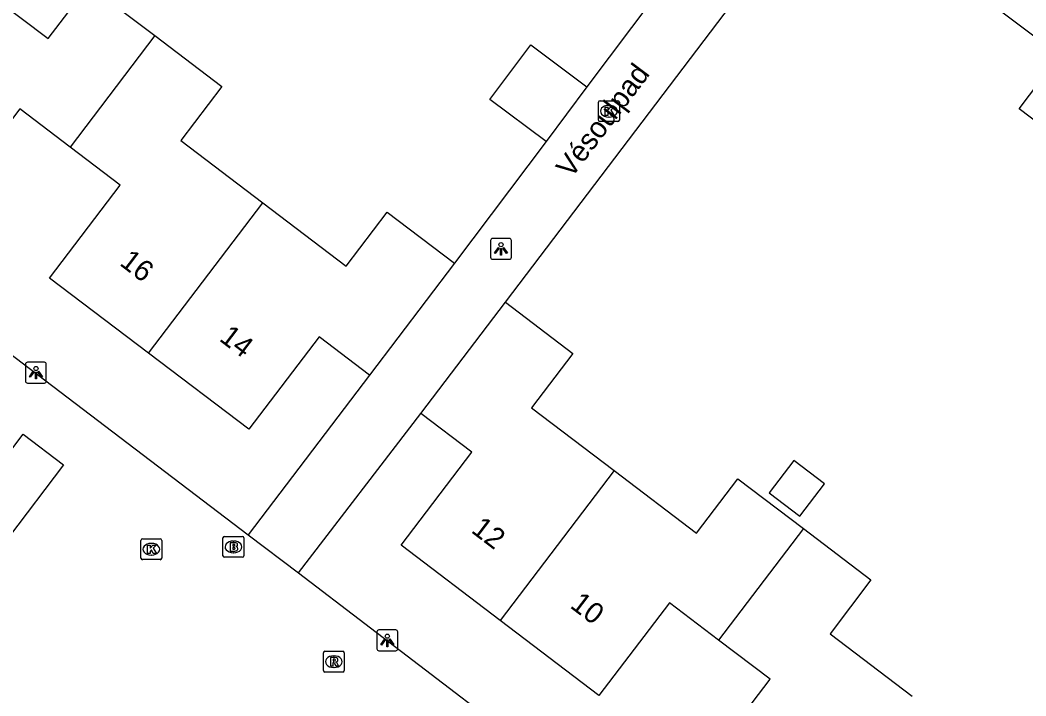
# Model space of a CAD drawing. Extents: x 158474 to 159560, y 388525 to 389605.
# Drawn here: x 158655.08 to 158703.27, y 389061.16 to 389093.56 of the extents above; entities that cross this region are included whole.
import ezdxf

# ---------------------------------------------------------------- set-up
doc = ezdxf.new("R2010")
doc.units = 0
for name, color, linetype in [('IMGEO_Brandkraan', 7, 'Continuous'), ('IMGEO_Kolk', 7, 'Continuous'), ('IMGEO_Lichtpunt', 7, 'Continuous'), ('IMGEO_Openbare_ruimte_label', 7, 'Continuous'), ('IMGEO_Pand', 7, 'Continuous'), ('IMGEO_Pand_nummerreeks', 7, 'Continuous'), ('IMGEO_Rijbaan_lokaal_open', 7, 'Continuous'), ('IMGEO_Rioolput', 7, 'Continuous')]:
    doc.layers.add(name, color=color, linetype=linetype)

msp = doc.modelspace()

# ---------------------------------------------------------------- linework, layer by layer
at = {"layer": 'IMGEO_Brandkraan'}
for p, q in [((158664.798, 389067.88), (158664.798, 389068.732)), ((158664.873, 389068.806), (158665.725, 389068.806)), ((158665.286, 389068.586), (158665.311, 389068.586)), ((158665.799, 389068.732), (158665.799, 389067.88)), ((158665.725, 389067.806), (158664.873, 389067.806)), ((158665.309, 389068.026), (158665.284, 389068.026))]:
    msp.add_line(p, q, dxfattribs=at)
for points in [[(158664.798, 389067.88), (158664.798, 389068.732)], [(158664.873, 389068.806), (158665.725, 389068.806)], [(158665.799, 389068.732), (158665.799, 389067.88)], [(158665.146, 389068.506), (158665.146, 389068.106), (158665.359, 389068.106)], [(158665.377, 389068.506), (158665.146, 389068.506)], [(158665.325, 389068.425), (158665.271, 389068.425), (158665.271, 389068.349)], [(158665.271, 389068.349), (158665.324, 389068.349)], [(158665.333, 389068.273), (158665.271, 389068.273), (158665.271, 389068.192)], [(158665.271, 389068.192), (158665.333, 389068.192)], [(158665.725, 389067.806), (158664.873, 389067.806)]]:
    msp.add_lwpolyline(points, dxfattribs=at)
for centre, radius, start, end in [((158664.875, 389068.73), 0.0765, 91.552, 178.448), ((158664.875, 389068.73), 0.0765, 91.552, 178.448), ((158665.723, 389068.73), 0.0765, 1.552, 88.448), ((158665.723, 389068.73), 0.0765, 1.552, 88.448), ((158665.326, 389068.387), 0.0379, 267.8285, 90.9355), ((158665.334, 389068.232), 0.0404, 269.8759, 90.5077), ((158665.365, 389068.357), 0.251, 268.6676, 293.5347), ((158665.381, 389068.361), 0.145, 59.4692, 91.5367), ((158665.406, 389068.408), 0.0922, 285.5137, 58.1501), ((158665.411, 389068.216), 0.105, 301.3115, 78.989), ((158664.875, 389067.882), 0.0765, 181.552, 268.448), ((158664.875, 389067.882), 0.0765, 181.552, 268.448), ((158665.723, 389067.882), 0.0765, 271.552, 358.448), ((158665.723, 389067.882), 0.0765, 271.552, 358.448)]:
    msp.add_arc(centre, radius, start, end, dxfattribs=at)
for centre, major_axis, ratio, start_param, end_param in [((158665.285, 389068.306), (-0.387, 0.002), 0.722429, 4.712389, 7.853982), ((158665.31, 389068.306), (-0.39, 0.002), 0.717154, 1.570796, 4.712389)]:
    msp.add_ellipse(centre, major_axis=major_axis, ratio=ratio, start_param=start_param, end_param=end_param, dxfattribs=at)
at = {"layer": 'IMGEO_Kolk'}
for p, q in [((158682.79, 389088.768), (158682.79, 389089.62)), ((158682.865, 389089.694), (158683.717, 389089.694)), ((158683.278, 389089.474), (158683.303, 389089.474)), ((158683.791, 389089.62), (158683.791, 389088.768)), ((158683.301, 389088.914), (158683.276, 389088.914)), ((158683.717, 389088.694), (158682.865, 389088.694)), ((158660.865, 389067.767), (158660.865, 389068.619)), ((158660.94, 389068.693), (158661.792, 389068.693)), ((158661.866, 389068.619), (158661.866, 389067.767)), ((158661.353, 389068.473), (158661.378, 389068.473)), ((158661.792, 389067.693), (158660.94, 389067.693)), ((158661.376, 389067.913), (158661.351, 389067.913))]:
    msp.add_line(p, q, dxfattribs=at)
for points in [[(158682.79, 389088.768), (158682.79, 389089.62)], [(158682.865, 389089.694), (158683.717, 389089.694)], [(158683.111, 389089.394), (158683.234, 389089.394), (158683.234, 389089.243), (158683.364, 389089.394), (158683.528, 389089.394), (158683.382, 389089.243), (158683.535, 389088.994), (158683.383, 389088.994), (158683.298, 389089.158), (158683.234, 389089.091), (158683.234, 389088.994), (158683.111, 389088.994), (158683.111, 389089.394)], [(158683.791, 389089.62), (158683.791, 389088.768)], [(158683.717, 389088.694), (158682.865, 389088.694)], [(158660.865, 389067.767), (158660.865, 389068.619)], [(158660.94, 389068.693), (158661.792, 389068.693)], [(158661.866, 389068.619), (158661.866, 389067.767)], [(158661.186, 389068.393), (158661.309, 389068.393), (158661.309, 389068.242), (158661.439, 389068.393), (158661.603, 389068.393), (158661.457, 389068.242), (158661.61, 389067.993), (158661.458, 389067.993), (158661.373, 389068.157), (158661.309, 389068.09), (158661.309, 389067.993), (158661.186, 389067.993), (158661.186, 389068.393)], [(158661.792, 389067.693), (158660.94, 389067.693)]]:
    msp.add_lwpolyline(points, dxfattribs=at)
for centre, start, end in [((158682.867, 389089.618), 91.552, 178.448), ((158682.867, 389089.618), 91.552, 178.448), ((158683.715, 389089.618), 1.552, 88.448), ((158683.715, 389089.618), 1.552, 88.448), ((158682.867, 389088.77), 181.552, 268.448), ((158682.867, 389088.77), 181.552, 268.448), ((158683.715, 389088.77), 271.552, 358.448), ((158683.715, 389088.77), 271.552, 358.448), ((158660.942, 389068.617), 91.552, 178.448), ((158660.942, 389068.617), 91.552, 178.448), ((158661.79, 389068.617), 1.552, 88.448), ((158661.79, 389068.617), 1.552, 88.448), ((158660.942, 389067.769), 181.552, 268.448), ((158660.942, 389067.769), 181.552, 268.448), ((158661.79, 389067.769), 271.552, 358.448), ((158661.79, 389067.769), 271.552, 358.448)]:
    msp.add_arc(centre, 0.0765, start, end, dxfattribs=at)
for centre, major_axis, ratio, start_param, end_param in [((158683.277, 389089.194), (-0.387, 0.002), 0.722429, 4.712389, 7.853982), ((158683.302, 389089.194), (-0.39, 0.002), 0.717154, 1.570796, 4.712389), ((158661.352, 389068.193), (-0.387, 0.002), 0.722429, 4.712389, 7.853982), ((158661.377, 389068.193), (-0.39, 0.002), 0.717154, 1.570796, 4.712389)]:
    msp.add_ellipse(centre, major_axis=major_axis, ratio=ratio, start_param=start_param, end_param=end_param, dxfattribs=at)
at = {"layer": 'IMGEO_Lichtpunt'}
for p, q in [((158677.619, 389082.996), (158677.619, 389082.189)), ((158677.619, 389082.996), (158677.619, 389082.189)), ((158678.521, 389083.091), (158677.713, 389083.091)), ((158678.521, 389083.091), (158677.713, 389083.091)), ((158678.615, 389082.189), (158678.615, 389082.996)), ((158678.615, 389082.189), (158678.615, 389082.996)), ((158677.713, 389082.095), (158678.521, 389082.095)), ((158677.713, 389082.095), (158678.521, 389082.095)), ((158655.336, 389077.061), (158655.336, 389076.254)), ((158655.336, 389077.061), (158655.336, 389076.254)), ((158656.238, 389077.156), (158655.43, 389077.156)), ((158656.238, 389077.156), (158655.43, 389077.156)), ((158656.332, 389076.254), (158656.332, 389077.061)), ((158656.332, 389076.254), (158656.332, 389077.061)), ((158655.43, 389076.16), (158656.238, 389076.16)), ((158655.43, 389076.16), (158656.238, 389076.16)), ((158672.175, 389064.227), (158672.175, 389063.42)), ((158672.175, 389064.227), (158672.175, 389063.42)), ((158673.077, 389064.322), (158672.269, 389064.322)), ((158673.077, 389064.322), (158672.269, 389064.322)), ((158673.171, 389063.42), (158673.171, 389064.227)), ((158673.171, 389063.42), (158673.171, 389064.227)), ((158672.269, 389063.326), (158673.077, 389063.326)), ((158672.269, 389063.326), (158673.077, 389063.326))]:
    msp.add_line(p, q, dxfattribs=at)
for points in [[(158677.993, 389082.66), (158678.032, 389082.632), (158677.844, 389082.37), (158677.806, 389082.397), (158677.993, 389082.66)], [(158678.095, 389082.612), (158678.142, 389082.612), (158678.142, 389082.29), (158678.095, 389082.29), (158678.095, 389082.612)], [(158678.205, 389082.632), (158678.243, 389082.659), (158678.43, 389082.397), (158678.391, 389082.369), (158678.205, 389082.632)], [(158655.71, 389076.725), (158655.749, 389076.697), (158655.561, 389076.435), (158655.523, 389076.462), (158655.71, 389076.725)], [(158655.922, 389076.697), (158655.96, 389076.724), (158656.147, 389076.462), (158656.108, 389076.434), (158655.922, 389076.697)], [(158655.812, 389076.677), (158655.859, 389076.677), (158655.859, 389076.355), (158655.812, 389076.355), (158655.812, 389076.677)], [(158672.549, 389063.891), (158672.588, 389063.863), (158672.4, 389063.601), (158672.362, 389063.628), (158672.549, 389063.891)], [(158672.651, 389063.843), (158672.698, 389063.843), (158672.698, 389063.521), (158672.651, 389063.521), (158672.651, 389063.843)], [(158672.761, 389063.863), (158672.799, 389063.89), (158672.986, 389063.628), (158672.947, 389063.6), (158672.761, 389063.863)]]:
    msp.add_lwpolyline(points, dxfattribs=at)
for centre in [(158678.118, 389082.794), (158655.835, 389076.859), (158672.674, 389064.025)]:
    msp.add_circle(centre, 0.0994, dxfattribs=at)
for centre, start, end in [((158677.713, 389082.996), 90, 180), ((158677.713, 389082.996), 90, 180), ((158678.521, 389082.996), 0, 90), ((158678.521, 389082.996), 0, 90), ((158677.713, 389082.189), 180, 270), ((158677.713, 389082.189), 180, 270), ((158678.521, 389082.189), 270, 0), ((158678.521, 389082.189), 270, 360), ((158655.43, 389077.061), 90, 180), ((158655.43, 389077.061), 90, 180), ((158656.238, 389077.061), 0, 90), ((158656.238, 389077.061), 0, 90), ((158655.43, 389076.254), 180, 270), ((158655.43, 389076.254), 180, 270), ((158656.238, 389076.254), 270, 0), ((158656.238, 389076.254), 270, 360), ((158672.269, 389064.227), 90, 180), ((158672.269, 389064.227), 90, 180), ((158673.077, 389064.227), 0, 90), ((158673.077, 389064.227), 0, 90), ((158672.269, 389063.42), 180, 270), ((158672.269, 389063.42), 180, 270), ((158673.077, 389063.42), 270, 0), ((158673.077, 389063.42), 270, 360)]:
    msp.add_arc(centre, 0.0946, start, end, dxfattribs=at)
at = {"layer": 'IMGEO_Pand'}
for points in [[(158652.463, 389095.674), (158656.42, 389092.671), (158658.359, 389095.225), (158661.535, 389092.814)], [(158706.182, 389086.862), (158702.948, 389089.314), (158704.875, 389091.856), (158700.955, 389094.828)], [(158661.535, 389092.814), (158657.482, 389087.472)], [(158661.535, 389092.814), (158664.749, 389090.375), (158662.781, 389087.782), (158666.701, 389084.807)], [(158680.277, 389087.743), (158677.592, 389089.759), (158679.554, 389092.371), (158682.238, 389090.356)], [(158682.238, 389090.356), (158680.277, 389087.743)], [(158657.482, 389087.472), (158655.063, 389089.308), (158651.682, 389084.853), (158646.967, 389088.432)], [(158661.229, 389077.596), (158656.491, 389081.192), (158659.878, 389085.654), (158657.482, 389087.472)], [(158661.229, 389077.596), (158666.701, 389084.807)], [(158666.701, 389084.807), (158670.701, 389081.771), (158672.66, 389084.353), (158675.89, 389081.901)], [(158675.89, 389081.901), (158671.82, 389076.538)], [(158674.283, 389074.706), (158678.338, 389080.036)], [(158678.338, 389080.036), (158681.568, 389077.578), (158679.589, 389074.979), (158683.544, 389071.969)], [(158671.82, 389076.538), (158669.4, 389078.375), (158666.038, 389073.946), (158661.229, 389077.596)], [(158678.073, 389064.778), (158673.33, 389068.387), (158676.725, 389072.848), (158674.283, 389074.706)], [(158690.971, 389070.901), (158692.44, 389069.784), (158693.614, 389071.326), (158692.145, 389072.444), (158690.971, 389070.901)], [(158683.544, 389071.969), (158678.073, 389064.778)], [(158683.544, 389071.969), (158687.495, 389068.962), (158689.476, 389071.565), (158692.61, 389069.18)], [(158692.61, 389069.18), (158688.544, 389063.837)], [(158692.61, 389069.18), (158695.844, 389066.719), (158693.885, 389064.144), (158697.825, 389061.145)], [(158688.544, 389063.837), (158686.188, 389065.629), (158682.802, 389061.179), (158678.073, 389064.778)], [(158692.361, 389053.889), (158687.621, 389057.497), (158691.015, 389061.956), (158688.544, 389063.837)]]:
    msp.add_lwpolyline(points, dxfattribs=at)
at = {"layer": 'IMGEO_Rijbaan_lokaal_open'}
for points in [[(158601.848, 389145.539), (158600.426, 389141.831), (158604.336, 389132.54), (158605.841, 389128.964), (158616.4, 389103.871), (158618.796, 389104.84), (158666.009, 389068.886)], [(158688.657, 389098.904), (158682.238, 389090.356)], [(158678.338, 389080.036), (158691.779, 389097.78)], [(158680.277, 389087.743), (158675.89, 389081.901)], [(158671.82, 389076.538), (158666.009, 389068.886)], [(158668.409, 389067.056), (158674.283, 389074.706)], [(158652.585, 389070.22), (158655.228, 389073.702), (158657.155, 389072.238), (158654.513, 389068.757)], [(158666.009, 389068.886), (158668.409, 389067.056)], [(158668.409, 389067.056), (158697.03, 389045.201), (158703.674, 389029.291)]]:
    msp.add_lwpolyline(points, dxfattribs=at)
at = {"layer": 'IMGEO_Rioolput'}
for p, q in [((158669.609, 389062.377), (158669.609, 389063.229)), ((158669.684, 389063.303), (158670.536, 389063.303)), ((158670.61, 389063.229), (158670.61, 389062.377)), ((158670.097, 389063.083), (158670.122, 389063.083)), ((158670.536, 389062.303), (158669.684, 389062.303)), ((158670.12, 389062.523), (158670.095, 389062.523))]:
    msp.add_line(p, q, dxfattribs=at)
for points in [[(158669.609, 389062.377), (158669.609, 389063.229)], [(158669.684, 389063.303), (158670.536, 389063.303)], [(158670.61, 389063.229), (158670.61, 389062.377)], [(158670.198, 389063.001), (158669.946, 389063.003), (158669.946, 389062.603)], [(158669.946, 389062.603), (158670.07, 389062.603), (158670.07, 389062.765), (158670.081, 389062.765)], [(158670.124, 389062.922), (158670.07, 389062.922), (158670.07, 389062.841)], [(158670.07, 389062.841), (158670.122, 389062.841)], [(158670.536, 389062.303), (158669.684, 389062.303)], [(158670.128, 389062.736), (158670.199, 389062.603), (158670.339, 389062.603), (158670.274, 389062.729)]]:
    msp.add_lwpolyline(points, dxfattribs=at)
for centre, radius, start, end in [((158669.686, 389063.227), 0.0765, 91.552, 178.448), ((158669.686, 389063.227), 0.0765, 91.552, 178.448), ((158670.534, 389063.227), 0.0765, 1.552, 88.448), ((158670.534, 389063.227), 0.0765, 1.552, 88.448), ((158670.08, 389062.712), 0.0533, 26.0293, 88.6989), ((158670.106, 389063.03), 0.19, 274.7715, 282.9687), ((158670.13, 389062.826), 0.0964, 77.0061, 93.1865), ((158670.144, 389062.883), 0.0378, 276.6634, 79.6772), ((158670.197, 389062.891), 0.109, 350.3612, 89.416), ((158670.195, 389062.891), 0.112, 277.5842, 350.9817), ((158670.179, 389062.676), 0.108, 29.5134, 73.7905), ((158669.686, 389062.379), 0.0765, 181.552, 268.448), ((158669.686, 389062.379), 0.0765, 181.552, 268.448), ((158670.534, 389062.379), 0.0765, 271.552, 358.448), ((158670.534, 389062.379), 0.0765, 271.552, 358.448)]:
    msp.add_arc(centre, radius, start, end, dxfattribs=at)
for centre, major_axis, ratio, start_param, end_param in [((158670.096, 389062.803), (-0.387, 0.002), 0.722429, 4.712389, 7.853982), ((158670.121, 389062.803), (-0.39, 0.002), 0.717154, 1.570796, 4.712389)]:
    msp.add_ellipse(centre, major_axis=major_axis, ratio=ratio, start_param=start_param, end_param=end_param, dxfattribs=at)

# ---------------------------------------------------------------- texts
at = {"layer": 'IMGEO_Openbare_ruimte_label'}
msp.add_text('Vésoulpad', height=1, rotation=52.9696, dxfattribs=at).set_placement((158681.486, 389085.937))
at = {"layer": 'IMGEO_Pand_nummerreeks'}
for s, rotation, p in [('16', 322.8022, (158659.798, 389081.846)), ('14', 322.8022, (158664.572, 389078.223)), ('12', 322.7296, (158676.641, 389069.035)), ('10', 322.7296, (158681.381, 389065.427))]:
    msp.add_text(s, height=1, rotation=rotation, dxfattribs=at).set_placement(p)

doc.saveas('drawing.dxf')
